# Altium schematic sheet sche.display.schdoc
size 297 x 209 mm; Symbol: Sheet-Symbol_A4; Border: 1; Title Block Position: 3; Width: 1170; Height: 825; Region Start: 1; X Region Count: 6; Y Region Count: 4; Blade Width: 10; Title Block: 1; @Board Name: NandFlash; @Create Time: 20:22:53; @Update Time: 18:33:35; Company: 嘉立创EDA; Version: V1.0; Page Size: A4; @Project Name: 木马派(Mumap) Linux卡片电脑-RV1106G; @Page Count: 10; @Update Date: 2025-03-03; @Create Date: 2024-11-27; @Schematic Name: Schematic1; @Page No: 7; @Page Name: Display; Device: Sheet-Symbol_A4
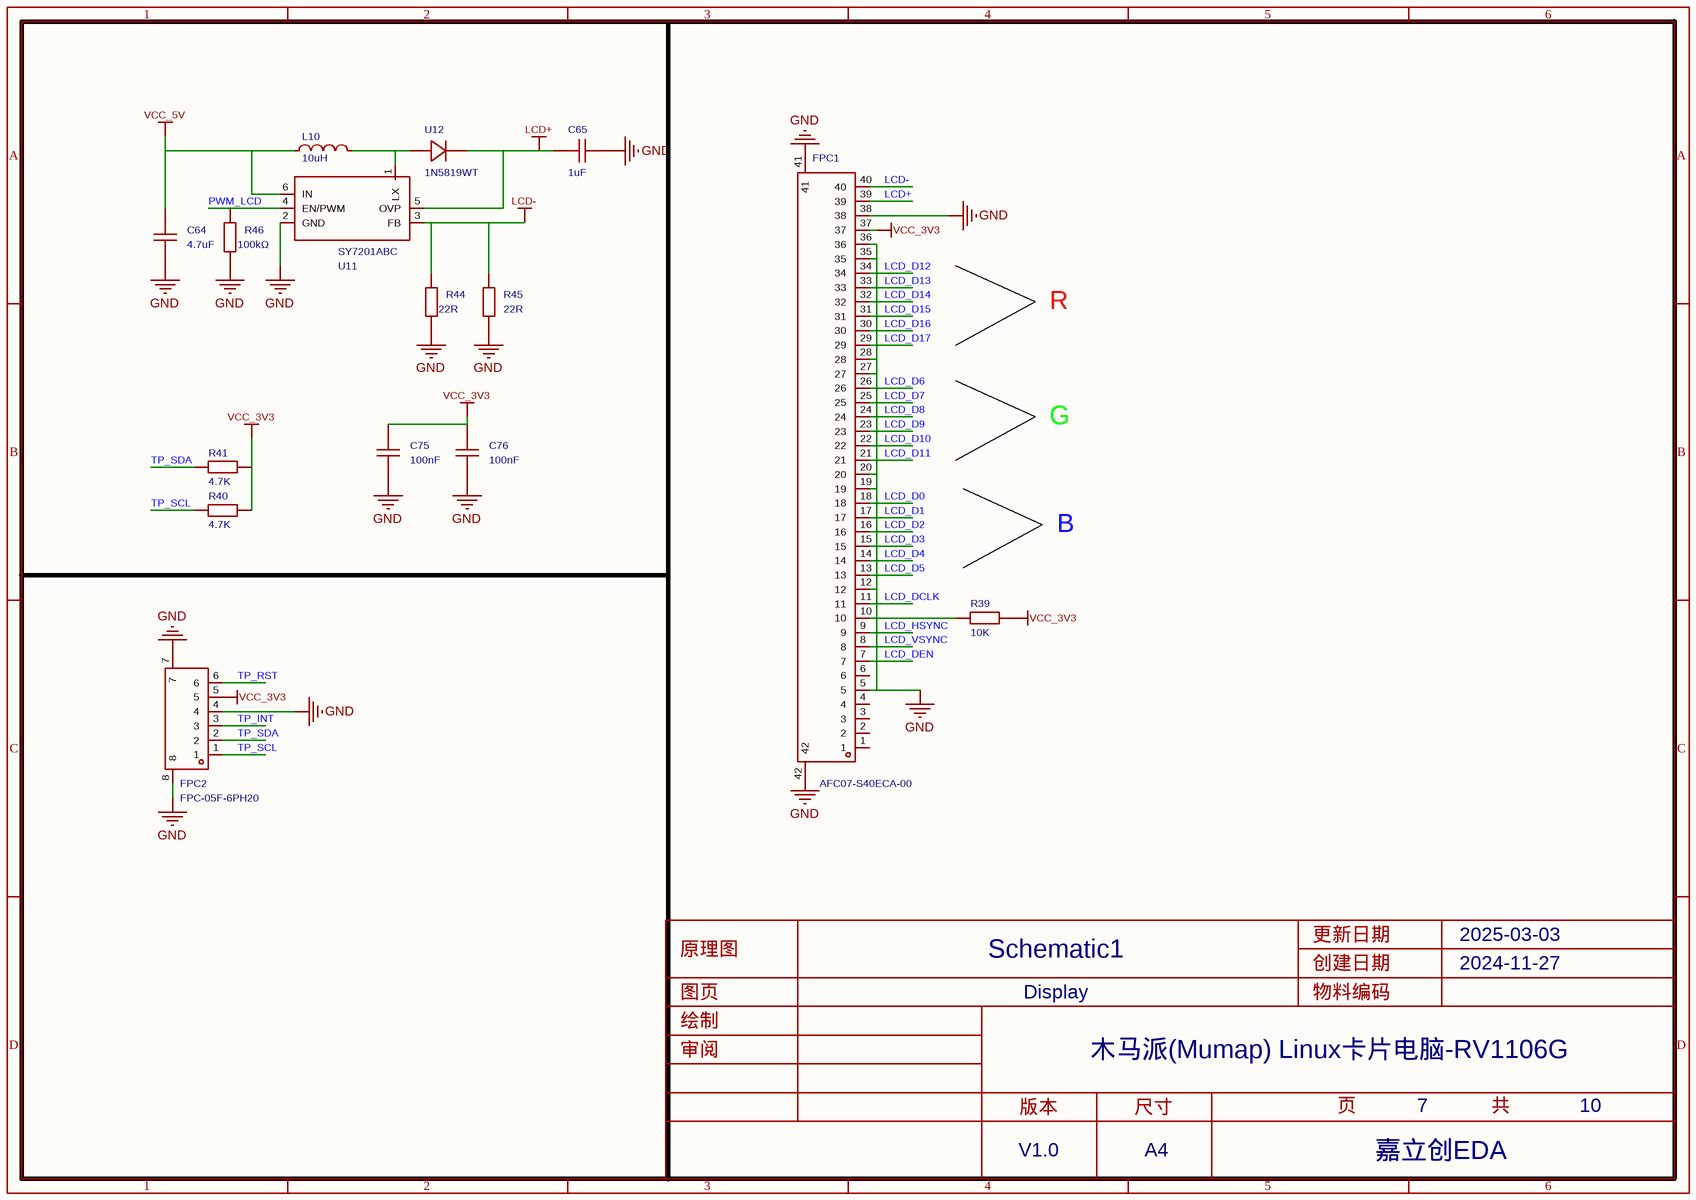
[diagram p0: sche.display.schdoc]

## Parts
C64  4.7uF  [C0603]
C65  1uF  [C0402]
C75  100nF  [C0402]
C76  100nF  [C0402]
FPC1  AFC07-S40ECA-00  [FPC-SMD_P0.50-40P_LCS-SJ-H2.0]
FPC2  FPC-05F-6PH20  [FPC-SMD_6P-P0.50_XUNPU_FPC-05F-6PH20]
L10  10uH  [IND-SMD_L3.0-W3.0_FNR30XXS]
R39  10K  [R0402]
R40  4.7K  [R0402]
R41  4.7K  [R0402]
R44  22R  [R0603]
R45  22R  [R0603]
R46  100kΩ  [R0402]
U11  SY7201ABC  [SOT-23-6_L2.9-W1.6-P0.95-LS2.8-BR]
U12  1N5819WT  [SOD-523_L1.2-W0.8-LS1.6-RD]

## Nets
GND: C64.1 C65.1 C75.1 C76.1 FPC1.5 FPC1.12 FPC1.19 FPC1.20 FPC1.27 FPC1.28 FPC1.35 FPC1.36 FPC1.38 FPC1.41 FPC1.42 FPC2.4 FPC2.7 FPC2.8 R44.1 R45.1 R46.1 U11.2(GND)
LCD+: C65.2 FPC1.39 U11.5(OVP) U12.1(K)
LCD-: FPC1.40 R44.2 R45.2 U11.3(FB)
VCC_3V3: C75.2 C76.2 FPC1.37 FPC2.5 R39.2 R40.1 R41.1
VCC_5V: C64.2 L10.1 U11.6(IN)
LCD_D0: FPC1.18
LCD_D1: FPC1.17
LCD_D2: FPC1.16
LCD_D3: FPC1.15
LCD_D4: FPC1.14
LCD_D5: FPC1.13
LCD_D6: FPC1.26
LCD_D7: FPC1.25
LCD_D8: FPC1.24
LCD_D9: FPC1.23
LCD_D10: FPC1.22
LCD_D11: FPC1.21
LCD_D12: FPC1.34
LCD_D13: FPC1.33
LCD_D14: FPC1.32
LCD_D15: FPC1.31
LCD_D16: FPC1.30
LCD_D17: FPC1.29
LCD_DCLK: FPC1.11
LCD_DEN: FPC1.7
LCD_HSYNC: FPC1.9
LCD_VSYNC: FPC1.8
PWM_LCD: R46.2 U11.4(EN/PWM)
TP_INT: FPC2.3
TP_RST: FPC2.6
TP_SCL: FPC2.1 R40.2
TP_SDA: FPC2.2 R41.2
NetFPC1_10: FPC1.10 R39.1
NetL10_2: L10.2 U11.1(LX) U12.2(A)

Not connected (* = marked no-connect by the designer): FPC1 1 2 3 4 6

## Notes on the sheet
- R
- G
- B

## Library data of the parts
C64 = CL10A475KA8NQNC: 容值:4.7uF;精度:±10%;额定电压:25V;材质(温度系数):X5R;; Manufacturer: SAMSUNG(三星); Symbol: CapAcitance; AddInBom: yes; ModelId: ac125912035d415993ca9572d50418b1; ModelName: C0603_L1.6-W0.8-H0.8; ModelTransform: 62.992,31.496,0,0,0,0,0,0,0; Tolerance: ±10%; Voltage Rated: 25V; Temperature Coefficient: X5R
C65 C75 C76 = CAP_0402: Symbol: CapAcitance; ConvertToPcb: yes; ModelId: 36a51122f27c49738f86b3bfa98863e0; ModelName: C0402_L1.0-W0.5-H0.5; ModelTransform: 39.37,19.685,0,0,0,0,0,0,0
FPC1 = AFC07-S40ECA-00: 锁定特性:抽屉式;触点类型:上接;触点数量:40P;间距:0.5mm;安装类型:卧贴;; Manufacturer: JS(钜硕电子); AddInBom: yes; ModelId: ed251399460347cf92383a49adf47404; ModelTransform: 1007.87192,226.3775,0,0,0,0,0,45.946,0; Locking Feature: 抽屉式; Number of Contacts: 40P; Pitch: 0.5mm; FFC, FCB Thickness: 0.3mm
FPC2 = FPC-05F-6PH20: 锁定特性:翻盖式;触点类型:下接;触点数量:6P;间距:0.5mm;安装类型:卧贴;工作温度范围:-25℃~+85℃;; Manufacturer: XUNPU(讯普); AddInBom: yes; ModelId: f0153d283bb647ab8cc6ddf5c8ee15be; ModelTransform: 291.338,220.472,0,0,0,0,-0.001,-45.276,0; Locking Feature: 翻盖式; Number of Contacts: 6P; Pitch: 0.5mm; FFC, FCB Thickness: 0.3mm
L10 = FNR3015S100MT: 电感值:10uH;精度:±20%;额定电流:900mA;饱和电流(Isat):920mA;; Manufacturer: cjiang(长江微电); AddInBom: yes; ModelId: 822d71758aa744dca2559abd61137eb2; ModelName: IND-SMD_L3.0-W3.0-H1.5_FNR30XXS; ModelTransform: 118.11,118.11,0,90,0,0,0,0,0; Tolerance: ±20%; Rated Current: 900mA; Saturation Current (Isat): 920mA; DC Resistance (DCR): 325mΩ
R39-R41 = Res_0402: Symbol: 电阻; ConvertToPcb: yes; ModelId: 671aefced39d4c318694bba8bd8efd39; ModelName: R0402_L1.0-W0.5-H0.5; ModelTransform: 39.37,19.685,0,0,0,0,0,0.0005,0
R44 = Res_0603: Symbol: 电阻; Check: false; ConvertToPcb: yes; ModelId: fc143cca1e79419f9cd78b61e9279f08; ModelTransform: 31.8897,63.7794,0,90,0,0,0,0,0
R45 = 0603WAF300KT5E: 电阻类型:厚膜电阻;阻值:3Ω;精度:±1%;功率:100mW;最大工作电压:75V;温度系数:±200ppm/℃;; Manufacturer: UNI-ROYAL(厚声); Symbol: 电阻; AddInBom: yes; ModelId: fc143cca1e79419f9cd78b61e9279f08; ModelTransform: 31.8897,63.7794,0,90,0,0,0,0,0; Tolerance: ±1%; Power(Watts): 100mW; Overload Voltage (Max): 75V
R46 = 0402WGF1003TCE: 电阻类型:厚膜电阻;阻值:100kΩ;精度:±1%;功率:62.5mW;最大工作电压:50V;温度系数:±100ppm/℃;; Manufacturer: UNI-ROYAL(厚声); Symbol: 电阻; AddInBom: yes; ModelId: 671aefced39d4c318694bba8bd8efd39; ModelName: R0402_L1.0-W0.5-H0.5; ModelTransform: 39.37,19.685,0,0,0,0,0,0.0005,0; Tolerance: ±1%; Power(Watts): 62.5mW; Overload Voltage (Max): 50V
U11 = SY7201ABC: Manufacturer: silergy(矽力杰); AddInBom: yes; ModelId: 18da8f6c14a34920b3e136b5c401a119; ModelName: SOT-23-6_L2.9-W1.6-H1.5-LS2.8-P0.95; ModelTransform: 110.73671,114.173,0,180,0,0,0.001,-0.003,0
U12 = 1N5819WT_C5451630: 二极管配置:独立式;正向压降(Vf):600mV@200mA;直流反向耐压(Vr):40V;整流电流:350mA;; Manufacturer: HXY MOSFET(华轩阳电子); AddInBom: yes; ModelId: 8f56a03db567494d8f4c9d12aa52a741; ModelName: SOD-523_L1.2-W0.8-H0.7-LS1.6; ModelTransform: 62.992,31.496,0,180,0,0,0,0,0; Diode Configuration: 独立式; Reverse Voltage (Vr): 40V; Rectified Current: 350mA; Reverse Leakage Current (Ir): 5uA@30V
